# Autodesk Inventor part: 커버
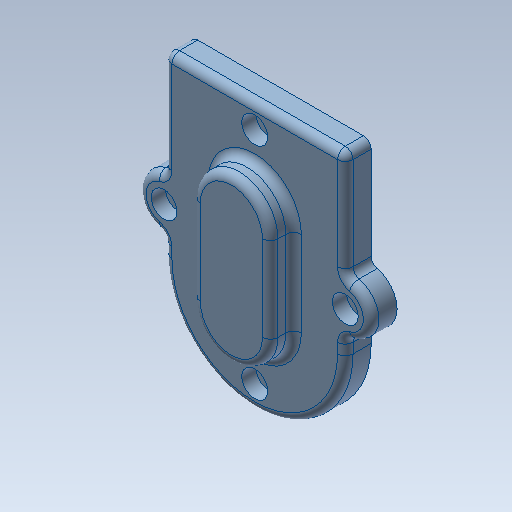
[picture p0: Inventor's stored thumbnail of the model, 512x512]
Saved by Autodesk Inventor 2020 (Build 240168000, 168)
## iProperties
Created: 2024-02
Part Number: 커버
Material: 알루미늄 6061
Document SubType Name: Modeling
Designer: mdu-01
Density: 1 g/cm^3
Appearance: 기본값(1)
Author: mdu-01
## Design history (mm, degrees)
sketch "스케치1"
  geometry: L1 (14, -3.702)-(14, -14.074) reference; L2 (-14, -14.074)-(-14, -3.702) reference; L3 (35, 3.761)-(35, 39.612) reference; L4 (32, 42.612)-(-32, 42.612) reference; L5 (-35, 39.612)-(-35, 3.761) reference; L6 (-35, -21.537)-(-35, -25.388) reference; L7 (35, -25.388)-(35, -21.537) reference; C1 r 2.75 at (0, -51.388) reference; C2 r 2.75 at (-35, -8.888) reference; C3 r 2.75 at (35, -8.888) reference; C4 r 2.75 at (0, 33.612) reference; A1 r 18 centre (0, 7.612) between (14, -3.702) and (-14, -3.702) reference; A2 r 18 centre (0, -25.388) between (-14, -14.074) and (14, -14.074) reference; A3 r 3 centre (38, 3.761) between (35, 3.761) and (37.308, 0.842) reference; A4 r 3 centre (32, 39.612) between (35, 39.612) and (32, 42.612) reference; A5 r 3 centre (-32, 39.612) between (-32, 42.612) and (-35, 39.612) reference; A6 r 3 centre (-38, 3.761) between (-37.308, 0.842) and (-35, 3.761) reference; A7 r 10 centre (-35, -8.888) between (-37.308, 0.842) and (-37.308, -18.618) reference; A8 r 3 centre (-38, -21.537) between (-35, -21.537) and (-37.308, -18.618) reference; A9 r 35 centre (0, -25.388) between (-35, -25.388) and (35, -25.388) reference; A10 r 3 centre (38, -21.537) between (37.308, -18.618) and (35, -21.537) reference; A11 r 10 centre (35, -8.888) between (37.308, -18.618) and (37.308, 0.842) reference; 1 further point
extrude "돌출1" new body sketch "스케치1" distance "d0" = 10; taper "d1" = 0 deg
sketch "스케치2"
  geometry: L1 (-15, 7.612)-(-15, -25.388); L2 (15, 7.612)-(15, -25.388); A1 r 15 centre (0, -25.388) between (-15, -25.388) and (15, -25.388); A2 r 15 centre (0, 7.612) between (15, 7.612) and (-15, 7.612); 3 further points
  constraints: 4 end point, 4 point on circle, 4 tangent, 2 centre point, 2 coincident
  dimensions: "d2" = 30 diameter of A1; "d3" = 30 diameter of A2
extrude "돌출2" join sketch "스케치2" distance "d4" = 9; taper "d5" = 0 deg
fillet "모깎기1" dims "d6" = 3
sketch "스케치3"
  geometry: L1 (-25.388, 0)-(-25.388, 14.041); L2 (-25.388, 16)-(-25.388, 19) reference; L3 (-25.388, 14.041)-(-18.388, 10); L4 (-18.388, 10)-(-15.388, 10); L5 (-15.388, 10)-(-15.388, 0); L6 (0.842, 0)-(-18.618, 0) reference; L7 (-15.388, 0)-(-25.388, 0); 2 further points
  constraints: 10 end point, 2 collinear, 1 parallel, 1 point on line
  dimensions: "d7" = 10 distance between parallel lines of L4 L7; "d9" = 14 diameter of L3.end L1; "d10" = 60 deg angle of L1 L3; "d11" = 20 diameter of L5 L1
revolve "회전1" sketch "스케치3" stored, may be unused: angle "d12" = 90 deg
chamfer "모따기1" distance "d13" = 1; stored, may be unused: second distance "d14" = 2, angle "d15" = 45 deg
sketch "스케치4"
  geometry: 5 further points
hole "구멍1" sketch "스케치4" at (35, -8.888), (-35, -8.888), (0, 33.612), (0, -51.388) diameter "d19" = 5.5; stored, may be unused: countersink angle "d23" = 90 deg, drill point angle "d25" = 118 deg; dims "d20" = 6, "d21" = 10, "d22" = 5.5, "d24" = 8
node "솔리드1"
pattern_linear "직사각형 패턴1" dims "d18" = 33
node "참조1"
